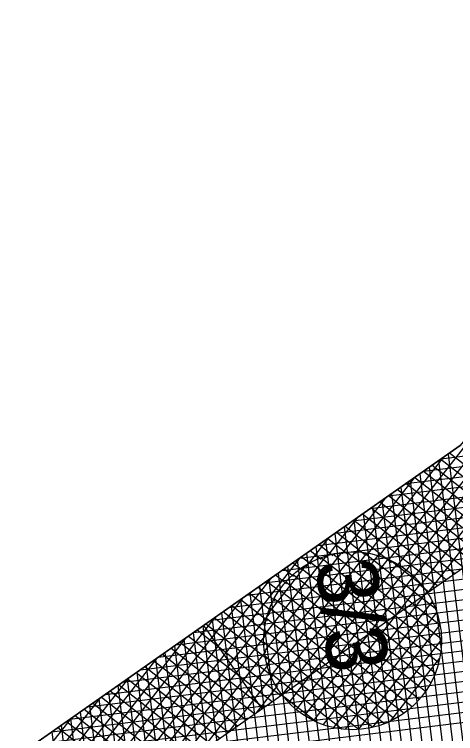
# Model space of a CAD drawing. Extents: x -566982 to -566809, y -1095912 to -1095685.
# Drawn here: x -566869.52 to -566860.84, y -1095795.86 to -1095781.72 of the extents above; entities that cross this region are included whole.
import ezdxf

# ---------------------------------------------------------------- set-up
doc = ezdxf.new("R2010")
doc.units = 0
for name, color, linetype in [('Vrstva 1', 7, 'Continuous'), ('Vrstva 40', 7, 'Continuous'), ('Vrstva 41', 7, 'Continuous'), ('Vrstva 42', 7, 'Continuous'), ('Vrstva 43', 7, 'Continuous'), ('Vrstva 44', 7, 'Continuous')]:
    doc.layers.add(name, color=color, linetype=linetype)

msp = doc.modelspace()

# ---------------------------------------------------------------- linework, layer by layer
at = {"layer": 'Vrstva 1'}
msp.add_line((-566887.09, -1095808.66), (-566860.75, -1095790.2), dxfattribs=at)
at = {"layer": 'Vrstva 41'}
for p, q in [((-566853.941, -1095781.951), (-566862.169, -1095792.466)), ((-566858.821, -1095787.863), (-566862.365, -1095792.392)), ((-566860.957, -1095790.345), (-566860.515, -1095790.691)), ((-566861.09, -1095790.438), (-566862.58, -1095792.343)), ((-566861.128, -1095790.465), (-566860.573, -1095790.9)), ((-566861.3, -1095790.585), (-566860.602, -1095791.131)), ((-566860.505, -1095790.664), (-566861.988, -1095792.56)), ((-566861.471, -1095790.705), (-566860.599, -1095791.388)), ((-566861.652, -1095790.832), (-566862.816, -1095792.32)), ((-566861.642, -1095790.825), (-566860.546, -1095791.683)), ((-566861.984, -1095791.065), (-566860.338, -1095792.354)), ((-566861.813, -1095790.945), (-566860.395, -1095792.055)), ((-566862.156, -1095791.185), (-566860.509, -1095792.474)), ((-566860.602, -1095791.113), (-566861.823, -1095792.673)), ((-566862.215, -1095791.226), (-566863.079, -1095792.331)), ((-566862.327, -1095791.305), (-566860.68, -1095792.594)), ((-566862.498, -1095791.425), (-566860.851, -1095792.714)), ((-566860.596, -1095791.43), (-566861.671, -1095792.803)), ((-566862.777, -1095791.621), (-566863.386, -1095792.399)), ((-566862.669, -1095791.545), (-566861.022, -1095792.834)), ((-566862.84, -1095791.665), (-566861.194, -1095792.954)), ((-566860.545, -1095791.688), (-566861.534, -1095792.953)), ((-566863.183, -1095791.905), (-566862.633, -1095792.336)), ((-566863.012, -1095791.785), (-566862.097, -1095792.501)), ((-566860.466, -1095791.913), (-566861.386, -1095793.089)), ((-566863.339, -1095792.015), (-566863.786, -1095792.586)), ((-566863.354, -1095792.025), (-566862.974, -1095792.323)), ((-566863.525, -1095792.145), (-566863.25, -1095792.361)), ((-566863.697, -1095792.265), (-566863.482, -1095792.433)), ((-566863.902, -1095792.409), (-566867.103, -1095796.5)), ((-566863.868, -1095792.385), (-566863.686, -1095792.527)), ((-566864.21, -1095792.625), (-566864.027, -1095792.769)), ((-566864.039, -1095792.505), (-566863.866, -1095792.64)), ((-566864.381, -1095792.745), (-566864.167, -1095792.913)), ((-566864.464, -1095792.803), (-566867.258, -1095796.374)), ((-566864.553, -1095792.865), (-566864.288, -1095793.072)), ((-566864.724, -1095792.985), (-566864.391, -1095793.245)), ((-566861.561, -1095792.92), (-566861.365, -1095793.074)), ((-566865.026, -1095793.197), (-566867.429, -1095796.268)), ((-566864.895, -1095793.105), (-566864.474, -1095793.434)), ((-566865.066, -1095793.225), (-566864.537, -1095793.639)), ((-566865.409, -1095793.465), (-566864.583, -1095794.111)), ((-566865.237, -1095793.345), (-566864.576, -1095793.863)), ((-566865.589, -1095793.591), (-566867.615, -1095796.181)), ((-566864.495, -1095793.492), (-566866.961, -1095796.644)), ((-566865.58, -1095793.585), (-566864.547, -1095794.393)), ((-566865.751, -1095793.705), (-566864.437, -1095794.733)), ((-566865.922, -1095793.825), (-566864.275, -1095795.113)), ((-566866.151, -1095793.985), (-566867.818, -1095796.115)), ((-566864.581, -1095793.926), (-566866.835, -1095796.807)), ((-566866.093, -1095793.945), (-566864.447, -1095795.233)), ((-566866.436, -1095794.185), (-566864.789, -1095795.473)), ((-566866.265, -1095794.065), (-566864.618, -1095795.353)), ((-566866.607, -1095794.305), (-566864.96, -1095795.593)), ((-566864.573, -1095794.241), (-566866.447, -1095796.636)), ((-566866.713, -1095794.379), (-566868.038, -1095796.072)), ((-566866.778, -1095794.425), (-566865.131, -1095795.713)), ((-566866.949, -1095794.545), (-566865.303, -1095795.833)), ((-566864.521, -1095794.498), (-566865.885, -1095796.241)), ((-566867.121, -1095794.665), (-566865.474, -1095795.953)), ((-566864.442, -1095794.722), (-566865.322, -1095795.847)), ((-566867.276, -1095794.773), (-566868.28, -1095796.057)), ((-566867.292, -1095794.785), (-566865.645, -1095796.073)), ((-566867.634, -1095795.025), (-566865.987, -1095796.313)), ((-566867.463, -1095794.905), (-566865.816, -1095796.193)), ((-566864.342, -1095794.919), (-566864.76, -1095795.453)), ((-566867.838, -1095795.167), (-566868.557, -1095796.086)), ((-566867.805, -1095795.145), (-566866.159, -1095796.433)), ((-566867.977, -1095795.265), (-566866.33, -1095796.553)), ((-566868.148, -1095795.385), (-566866.501, -1095796.673)), ((-566868.4, -1095795.562), (-566868.883, -1095796.178)), ((-566868.319, -1095795.505), (-566866.672, -1095796.793)), ((-566868.49, -1095795.625), (-566867.885, -1095796.098)), ((-566868.661, -1095795.745), (-566868.261, -1095796.058))]:
    msp.add_line(p, q, dxfattribs=at)
at = {"layer": 'Vrstva 42'}
msp.add_line((-566865.798, -1095793.738), (-566864.65, -1095795.376), dxfattribs=at)
msp.add_lwpolyline([(-566945.07, -1095716.34), (-566947.388, -1095716.328), (-566890.462, -1095814.681), (-566885.816, -1095810.21), (-566859.382, -1095791.684), (-566846.734, -1095776.361), (-566841.831, -1095758.448), (-566843.76, -1095757.92), (-566848.55, -1095775.42), (-566860.75, -1095790.2), (-566887.09, -1095808.66), (-566890.01, -1095811.47)], close=True, dxfattribs=at)
at = {"layer": 'Vrstva 43'}
for p, q in [((-566861.12, -1095790.459), (-566846.527, -1095788.678)), ((-566861.468, -1095790.703), (-566846.712, -1095788.902)), ((-566861.816, -1095790.947), (-566846.897, -1095789.126)), ((-566862.164, -1095791.191), (-566847.082, -1095789.351)), ((-566862.512, -1095791.435), (-566847.267, -1095789.575)), ((-566862.86, -1095791.679), (-566847.452, -1095789.799)), ((-566863.208, -1095791.923), (-566847.637, -1095790.023)), ((-566863.557, -1095792.167), (-566847.822, -1095790.247)), ((-566860.987, -1095790.366), (-566859.614, -1095801.615)), ((-566863.905, -1095792.411), (-566848.006, -1095790.471)), ((-566861.173, -1095790.496), (-566859.8, -1095801.745)), ((-566861.358, -1095790.626), (-566859.986, -1095801.875)), ((-566864.253, -1095792.655), (-566848.191, -1095790.695)), ((-566861.544, -1095790.756), (-566860.171, -1095802.005)), ((-566864.601, -1095792.899), (-566848.376, -1095790.919)), ((-566861.73, -1095790.887), (-566860.357, -1095802.135)), ((-566861.915, -1095791.017), (-566860.543, -1095802.265)), ((-566864.949, -1095793.143), (-566848.561, -1095791.143)), ((-566862.101, -1095791.147), (-566860.728, -1095802.396)), ((-566862.286, -1095791.277), (-566860.914, -1095802.526)), ((-566865.297, -1095793.387), (-566848.746, -1095791.367)), ((-566862.472, -1095791.407), (-566861.099, -1095802.656)), ((-566865.645, -1095793.631), (-566848.931, -1095791.591)), ((-566862.658, -1095791.537), (-566861.285, -1095802.786)), ((-566862.843, -1095791.667), (-566861.471, -1095802.916)), ((-566865.993, -1095793.875), (-566849.116, -1095791.815)), ((-566863.029, -1095791.797), (-566861.656, -1095803.046)), ((-566866.341, -1095794.119), (-566849.301, -1095792.039)), ((-566863.4, -1095792.057), (-566862.027, -1095803.306)), ((-566863.215, -1095791.927), (-566861.842, -1095803.176)), ((-566863.586, -1095792.187), (-566862.213, -1095803.436)), ((-566866.689, -1095794.363), (-566849.486, -1095792.263)), ((-566863.771, -1095792.317), (-566862.399, -1095803.566)), ((-566867.038, -1095794.607), (-566849.671, -1095792.487)), ((-566863.957, -1095792.448), (-566862.584, -1095803.696)), ((-566864.143, -1095792.578), (-566862.77, -1095803.827)), ((-566867.386, -1095794.851), (-566849.856, -1095792.711)), ((-566864.328, -1095792.708), (-566862.955, -1095803.957)), ((-566864.514, -1095792.838), (-566863.141, -1095804.087)), ((-566867.734, -1095795.094), (-566850.041, -1095792.935)), ((-566864.699, -1095792.968), (-566863.327, -1095804.217)), ((-566868.082, -1095795.338), (-566850.226, -1095793.159)), ((-566864.885, -1095793.098), (-566863.512, -1095804.347)), ((-566865.071, -1095793.228), (-566863.698, -1095804.477)), ((-566868.43, -1095795.582), (-566850.411, -1095793.384)), ((-566865.256, -1095793.358), (-566863.884, -1095804.607)), ((-566868.778, -1095795.826), (-566850.596, -1095793.608)), ((-566865.627, -1095793.618), (-566864.255, -1095804.867)), ((-566865.442, -1095793.488), (-566864.069, -1095804.737)), ((-566865.813, -1095793.748), (-566864.44, -1095804.997)), ((-566869.126, -1095796.07), (-566850.781, -1095793.832)), ((-566865.999, -1095793.878), (-566864.626, -1095805.127)), ((-566866.184, -1095794.009), (-566864.812, -1095805.257)), ((-566869.474, -1095796.314), (-566850.966, -1095794.056)), ((-566866.37, -1095794.139), (-566864.997, -1095805.388)), ((-566869.822, -1095796.558), (-566851.151, -1095794.28)), ((-566866.555, -1095794.269), (-566865.183, -1095805.518)), ((-566866.741, -1095794.399), (-566865.368, -1095805.648)), ((-566870.17, -1095796.802), (-566851.336, -1095794.504)), ((-566866.927, -1095794.529), (-566865.554, -1095805.778)), ((-566867.112, -1095794.659), (-566865.74, -1095805.908)), ((-566867.298, -1095794.789), (-566865.925, -1095806.038)), ((-566867.484, -1095794.919), (-566866.111, -1095806.168)), ((-566867.669, -1095795.049), (-566866.296, -1095806.298)), ((-566868.04, -1095795.309), (-566866.668, -1095806.558)), ((-566867.855, -1095795.179), (-566866.482, -1095806.428)), ((-566868.226, -1095795.439), (-566866.853, -1095806.688)), ((-566868.412, -1095795.57), (-566867.039, -1095806.818)), ((-566868.597, -1095795.7), (-566867.224, -1095806.949)), ((-566868.783, -1095795.83), (-566867.41, -1095807.079))]:
    msp.add_line(p, q, dxfattribs=at)
msp.add_lwpolyline([(-566834.15, -1095760.69), (-566843.76, -1095757.92), (-566848.55, -1095775.42), (-566860.75, -1095790.2), (-566887.09, -1095808.66), (-566890.01, -1095811.47), (-566945.07, -1095716.34), (-566956.66, -1095716.28), (-566892.27, -1095827.53), (-566880.71, -1095816.4), (-566853.9, -1095797.61), (-566839.47, -1095780.13)], close=True, dxfattribs=at)
at = {"layer": 'Vrstva 44'}
for p, q in [((-566863.081, -1095792.302), (-566864.603, -1095794.247)), ((-566862.817, -1095792.289), (-566864.551, -1095794.505)), ((-566862.581, -1095792.312), (-566864.472, -1095794.729)), ((-566863.252, -1095792.332), (-566861.117, -1095794.003)), ((-566862.979, -1095792.292), (-566861.146, -1095793.726)), ((-566862.641, -1095792.303), (-566861.238, -1095793.4)), ((-566863.386, -1095792.368), (-566864.613, -1095793.936)), ((-566862.365, -1095792.361), (-566864.372, -1095794.926)), ((-566862.168, -1095792.434), (-566864.254, -1095795.1)), ((-566863.488, -1095792.402), (-566861.131, -1095794.246)), ((-566862.12, -1095792.456), (-566861.508, -1095792.935)), ((-566863.779, -1095792.545), (-566864.533, -1095793.508)), ((-566861.987, -1095792.526), (-566864.121, -1095795.254)), ((-566863.873, -1095792.608), (-566861.237, -1095794.671)), ((-566863.692, -1095792.496), (-566861.171, -1095794.469)), ((-566864.035, -1095792.736), (-566861.323, -1095794.858)), ((-566861.819, -1095792.637), (-566863.974, -1095795.391)), ((-566861.666, -1095792.766), (-566863.813, -1095795.509)), ((-566864.178, -1095792.878), (-566861.428, -1095795.03)), ((-566861.526, -1095792.912), (-566863.636, -1095795.607)), ((-566864.3, -1095793.036), (-566861.55, -1095795.188)), ((-566861.403, -1095793.079), (-566863.444, -1095795.687)), ((-566864.405, -1095793.208), (-566861.69, -1095795.333)), ((-566861.297, -1095793.268), (-566863.237, -1095795.747)), ((-566864.492, -1095793.394), (-566861.851, -1095795.461)), ((-566861.209, -1095793.479), (-566863.008, -1095795.779)), ((-566864.559, -1095793.595), (-566862.032, -1095795.573)), ((-566861.146, -1095793.724), (-566862.758, -1095795.783)), ((-566864.601, -1095793.817), (-566862.235, -1095795.668)), ((-566861.117, -1095794.012), (-566862.47, -1095795.74)), ((-566864.615, -1095794.06), (-566862.468, -1095795.739)), ((-566864.589, -1095794.334), (-566862.738, -1095795.782)), ((-566861.152, -1095794.381), (-566862.122, -1095795.62)), ((-566864.501, -1095794.656), (-566863.072, -1095795.774)), ((-566864.247, -1095795.109), (-566863.575, -1095795.635))]:
    msp.add_line(p, q, dxfattribs=at)
msp.add_circle((-566862.866, -1095794.037), 1.75, dxfattribs=at)

# ---------------------------------------------------------------- texts
at = {"layer": 'Vrstva 40'}
msp.add_text('3/3', height=1.2, rotation=276.9575, dxfattribs=at).set_placement((-566863.599, -1095792.494))

doc.saveas('drawing.dxf')
